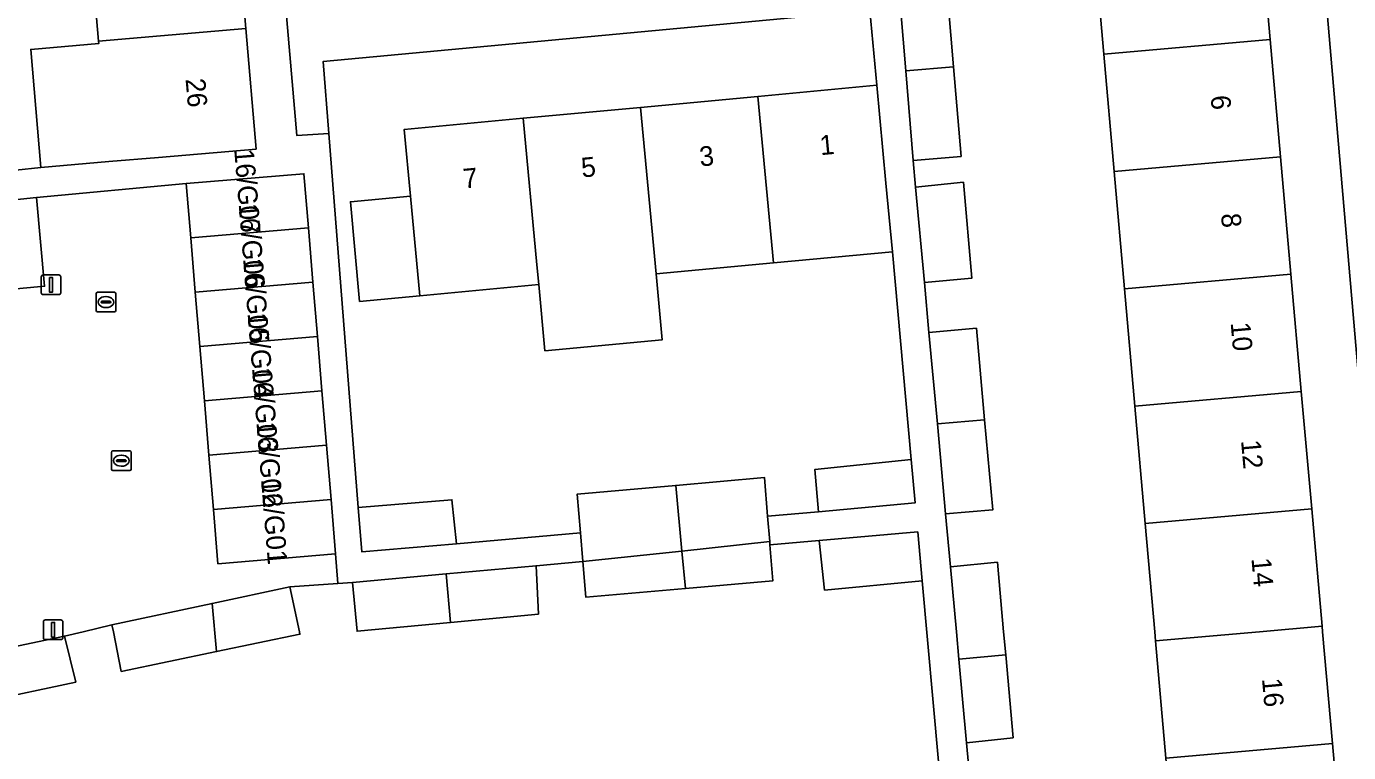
# Model space of a CAD drawing. Extents: x 160554 to 161248, y 385329 to 386506.
# Drawn here: x 160851.7 to 160919, y 385493.8 to 385530.8 of the extents above; entities that cross this region are included whole.
import ezdxf

# ---------------------------------------------------------------- set-up
doc = ezdxf.new("R2010")
doc.units = 0
for name, color, linetype in [('IMGEO_Erf', 7, 'Continuous'), ('IMGEO_Kolk', 7, 'Continuous'), ('IMGEO_Lichtmast', 7, 'Continuous'), ('IMGEO_Pand', 7, 'Continuous'), ('IMGEO_Pand_nummerreeks', 7, 'Continuous'), ('IMGEO_Rijbaan_lokaal_open', 7, 'Continuous'), ('IMGEO_Voetpad_open', 7, 'Continuous')]:
    doc.layers.add(name, color=color, linetype=linetype)

msp = doc.modelspace()

# ---------------------------------------------------------------- linework, layer by layer
at = {"layer": 'IMGEO_Erf'}
for points in [[(160847.33, 385523.103), (160852.438, 385523.647), (160851.923, 385529.66), (160855.383, 385529.957), (160855.372, 385530.081), (160854.859, 385536.059), (160854.347, 385542.038), (160853.835, 385548.016), (160853.735, 385549.177), (160853.308, 385554.158), (160850.795, 385554.015)], [(160922.169, 385482.49), (160920.66, 385500), (160917.04, 385541.995)], [(160898.533, 385533.424), (160898.921, 385528.774), (160899.302, 385524.209), (160896.864, 385524.005), (160896.988, 385522.65), (160899.419, 385522.893), (160899.857, 385518.014), (160897.434, 385517.787), (160897.668, 385515.238), (160900.086, 385515.454), (160900.503, 385510.798), (160900.915, 385506.204), (160898.514, 385506.003), (160898.761, 385503.314), (160901.154, 385503.536), (160901.471, 385500), (160901.577, 385498.816), (160901.955, 385494.597), (160899.584, 385494.338), (160899.871, 385491.211)], [(160898.156, 385493.385), (160897.322, 385502.59), (160892.348, 385502.123), (160892.083, 385504.64), (160889.57, 385504.418), (160889.721, 385502.597), (160885.262, 385502.205), (160880.193, 385501.759), (160880.036, 385503.585), (160877.659, 385503.363), (160877.777, 385500.899), (160873.294, 385500.473), (160868.541, 385500.022), (160868.309, 385502.512), (160867.569, 385502.46), (160865.12, 385502.288), (160865.605, 385500), (160865.632, 385499.874), (160861.382, 385498.99), (160856.532, 385497.982), (160856.127, 385500), (160856.058, 385500.345), (160854.586, 385500), (160853.634, 385499.777), (160854.211, 385497.44), (160849.566, 385496.443)]]:
    msp.add_lwpolyline(points, dxfattribs=at)
for points in [[(160907.099, 385523.44), (160906.571, 385529.417), (160906.043, 385535.394), (160905.5, 385541.541), (160913.975, 385542.309), (160914.52, 385536.143), (160915.048, 385530.166), (160915.575, 385524.189), (160916.103, 385518.213), (160916.631, 385512.236), (160917.159, 385506.259), (160917.687, 385500.282), (160917.712, 385500), (160918.215, 385494.306), (160918.76, 385488.141), (160910.284, 385487.387), (160909.739, 385493.557), (160909.211, 385499.533), (160909.17, 385500), (160908.683, 385505.51), (160908.155, 385511.487), (160907.627, 385517.464)], [(160895.804, 385519.357), (160889.741, 385518.792), (160883.767, 385518.234), (160884.08, 385514.87), (160878.105, 385514.314), (160877.792, 385517.677), (160871.731, 385517.112), (160868.671, 385516.827), (160868.198, 385521.898), (160871.258, 385522.184), (160870.94, 385525.585), (160877.003, 385526.15), (160882.978, 385526.708), (160888.952, 385527.265), (160895.014, 385527.83), (160894.659, 385531.64), (160866.822, 385529.049), (160867.099, 385525.38), (160868.589, 385506.326), (160873.368, 385506.726), (160873.599, 385504.474), (160879.912, 385505.035), (160879.743, 385507.006), (160884.773, 385507.454), (160889.284, 385507.856), (160889.448, 385505.888), (160892.046, 385506.113), (160891.849, 385508.261), (160896.763, 385508.775)]]:
    msp.add_lwpolyline(points, close=True, dxfattribs=at)
at = {"layer": 'IMGEO_Kolk'}
for p, q in [((160855.252, 385516.364), (160855.252, 385517.216)), ((160855.327, 385517.29), (160856.179, 385517.29)), ((160856.253, 385517.216), (160856.253, 385516.364)), ((160855.511, 385516.784), (160855.511, 385516.796)), ((160855.949, 385516.747), (160855.551, 385516.747)), ((160855.554, 385516.833), (160855.952, 385516.833)), ((160855.763, 385516.51), (160855.738, 385516.51)), ((160855.74, 385517.07), (160855.765, 385517.07)), ((160855.995, 385516.796), (160855.995, 385516.784)), ((160856.179, 385516.29), (160855.327, 385516.29)), ((160856.033, 385508.285), (160856.033, 385509.137)), ((160856.108, 385509.211), (160856.96, 385509.211)), ((160857.034, 385509.137), (160857.034, 385508.285)), ((160856.292, 385508.705), (160856.292, 385508.717)), ((160856.73, 385508.668), (160856.332, 385508.668)), ((160856.335, 385508.754), (160856.733, 385508.754)), ((160856.544, 385508.431), (160856.519, 385508.431)), ((160856.521, 385508.991), (160856.546, 385508.991)), ((160856.776, 385508.717), (160856.776, 385508.705)), ((160856.96, 385508.211), (160856.108, 385508.211))]:
    msp.add_line(p, q, dxfattribs=at)
for points in [[(160855.252, 385516.364), (160855.252, 385517.216)], [(160855.327, 385517.29), (160856.179, 385517.29)], [(160856.253, 385517.216), (160856.253, 385516.364)], [(160856.179, 385516.29), (160855.327, 385516.29)], [(160856.033, 385508.285), (160856.033, 385509.137)], [(160856.108, 385509.211), (160856.96, 385509.211)], [(160857.034, 385509.137), (160857.034, 385508.285)], [(160856.96, 385508.211), (160856.108, 385508.211)]]:
    msp.add_lwpolyline(points, dxfattribs=at)
for centre, radius, start, end in [((160855.329, 385517.214), 0.0765, 91.55205, 178.44795), ((160855.329, 385517.214), 0.0765, 91.55205, 178.44795), ((160856.177, 385517.214), 0.0765, 1.55205, 88.44795), ((160856.177, 385517.214), 0.0765, 1.55205, 88.44795), ((160855.551, 385516.793), 0.0403, 85.87752, 175.75265), ((160855.548, 385516.783), 0.0366, 178.93798, 274.71019), ((160855.952, 385516.79), 0.043, 264.86636, 352.45326), ((160855.956, 385516.795), 0.0386, 1.73085, 96.63898), ((160855.329, 385516.366), 0.0765, 181.55205, 268.44795), ((160855.329, 385516.366), 0.0765, 181.55205, 268.44795), ((160856.177, 385516.366), 0.0765, 271.55205, 358.44795), ((160856.177, 385516.366), 0.0765, 271.55205, 358.44795), ((160856.11, 385509.135), 0.0765, 91.55205, 178.44795), ((160856.11, 385509.135), 0.0765, 91.55205, 178.44795), ((160856.958, 385509.135), 0.0765, 1.55205, 88.44795), ((160856.958, 385509.135), 0.0765, 1.55205, 88.44795), ((160856.332, 385508.714), 0.0403, 85.87752, 175.75265), ((160856.329, 385508.704), 0.0366, 178.93798, 274.71019), ((160856.733, 385508.711), 0.043, 264.86636, 352.45326), ((160856.737, 385508.716), 0.0386, 1.73085, 96.63898), ((160856.11, 385508.287), 0.0765, 181.55205, 268.44795), ((160856.11, 385508.287), 0.0765, 181.55205, 268.44795), ((160856.958, 385508.287), 0.0765, 271.55205, 358.44795), ((160856.958, 385508.287), 0.0765, 271.55205, 358.44795)]:
    msp.add_arc(centre, radius, start, end, dxfattribs=at)
for centre, major_axis, ratio, start_param, end_param in [((160855.739, 385516.79), (-0.387, 0.002), 0.722429, 4.712389, 7.853982), ((160855.764, 385516.79), (-0.39, 0.002), 0.717154, 1.570796, 4.712389), ((160856.52, 385508.711), (-0.387, 0.002), 0.722429, 4.712389, 7.853982), ((160856.545, 385508.711), (-0.39, 0.002), 0.717154, 1.570796, 4.712389)]:
    msp.add_ellipse(centre, major_axis=major_axis, ratio=ratio, start_param=start_param, end_param=end_param, dxfattribs=at)
at = {"layer": 'IMGEO_Lichtmast'}
for p, q in [((160852.458, 385517.269), (160852.458, 385518.069)), ((160852.458, 385518.069), (160852.458, 385517.269)), ((160852.558, 385518.169), (160853.348, 385518.169)), ((160853.348, 385518.169), (160852.558, 385518.169)), ((160853.448, 385518.069), (160853.448, 385517.269)), ((160853.448, 385517.269), (160853.448, 385518.069)), ((160853.348, 385517.169), (160852.558, 385517.169)), ((160852.558, 385517.169), (160853.348, 385517.169)), ((160852.566, 385499.699), (160852.566, 385500.499)), ((160852.566, 385500.499), (160852.566, 385499.699)), ((160852.666, 385500.599), (160853.456, 385500.599)), ((160853.456, 385500.599), (160852.666, 385500.599)), ((160853.556, 385500.499), (160853.556, 385499.699)), ((160853.556, 385499.699), (160853.556, 385500.499)), ((160853.456, 385499.599), (160852.666, 385499.599)), ((160852.666, 385499.599), (160853.456, 385499.599))]:
    msp.add_line(p, q, dxfattribs=at)
for points in [[(160852.878, 385518.044), (160853.028, 385518.044), (160853.028, 385517.294), (160852.878, 385517.294), (160852.878, 385518.044)], [(160852.986, 385500.474), (160853.136, 385500.474), (160853.136, 385499.724), (160852.986, 385499.724), (160852.986, 385500.474)]]:
    msp.add_lwpolyline(points, dxfattribs=at)
for centre, start, end in [((160852.558, 385518.069), 90, 180), ((160852.558, 385518.069), 90, 180), ((160853.348, 385518.069), 0, 90), ((160853.348, 385518.069), 360, 90), ((160852.558, 385517.269), 180, 270), ((160852.558, 385517.269), 180, 270), ((160853.348, 385517.269), 270, 0), ((160853.348, 385517.269), 270, 0), ((160852.666, 385500.499), 90, 180), ((160852.666, 385500.499), 90, 180), ((160853.456, 385500.499), 0, 90), ((160853.456, 385500.499), 360, 90), ((160852.666, 385499.699), 180, 270), ((160852.666, 385499.699), 180, 270), ((160853.456, 385499.699), 270, 0), ((160853.456, 385499.699), 270, 0)]:
    msp.add_arc(centre, 0.1, start, end, dxfattribs=at)
at = {"layer": 'IMGEO_Pand'}
for points in [[(160862.874, 385530.724), (160862.361, 385536.702), (160854.859, 385536.059), (160855.372, 385530.081)], [(160906.043, 385535.394), (160906.571, 385529.417), (160915.048, 385530.166), (160914.52, 385536.143)], [(160896.215, 385531.785), (160896.484, 385528.559), (160898.921, 385528.774), (160898.533, 385533.424), (160896.095, 385533.221)], [(160862.874, 385530.724), (160855.372, 385530.081), (160855.383, 385529.957), (160851.923, 385529.66), (160852.438, 385523.647), (160855.898, 385523.943), (160858.419, 385524.159), (160863.4, 385524.586)], [(160915.575, 385524.189), (160915.048, 385530.166), (160906.571, 385529.417), (160907.099, 385523.44)], [(160896.484, 385528.559), (160896.864, 385524.005), (160899.302, 385524.209), (160898.921, 385528.774)], [(160888.952, 385527.265), (160882.978, 385526.708), (160883.767, 385518.234), (160889.741, 385518.792)], [(160889.741, 385518.792), (160895.804, 385519.357), (160895.478, 385522.852), (160895.014, 385527.83), (160888.952, 385527.265)], [(160882.978, 385526.708), (160877.003, 385526.15), (160877.699, 385518.679), (160877.792, 385517.677), (160878.105, 385514.314), (160884.08, 385514.87), (160883.767, 385518.234)], [(160877.003, 385526.15), (160870.94, 385525.585), (160871.258, 385522.184), (160871.731, 385517.112), (160877.792, 385517.677), (160877.699, 385518.679)], [(160907.099, 385523.44), (160907.627, 385517.464), (160916.103, 385518.213), (160915.575, 385524.189)], [(160865.831, 385523.329), (160859.84, 385522.83), (160860.07, 385520.064), (160866.061, 385520.563)], [(160899.857, 385518.014), (160899.419, 385522.893), (160896.988, 385522.65), (160897.434, 385517.787)], [(160848.46, 385517.218), (160852.623, 385517.592), (160852.215, 385522.108), (160848.142, 385521.699)], [(160871.258, 385522.184), (160868.198, 385521.898), (160868.671, 385516.827), (160871.731, 385517.112)], [(160860.07, 385520.064), (160860.301, 385517.297), (160866.292, 385517.796), (160866.061, 385520.563)], [(160866.522, 385515.03), (160866.292, 385517.796), (160860.301, 385517.297), (160860.531, 385514.531)], [(160916.631, 385512.236), (160916.103, 385518.213), (160907.627, 385517.464), (160908.155, 385511.487)], [(160900.503, 385510.798), (160900.086, 385515.454), (160897.668, 385515.238), (160898.094, 385510.585)], [(160866.753, 385512.263), (160866.522, 385515.03), (160860.531, 385514.531), (160860.762, 385511.764)], [(160866.983, 385509.497), (160866.753, 385512.263), (160860.762, 385511.764), (160860.992, 385508.998)], [(160917.159, 385506.259), (160916.631, 385512.236), (160908.155, 385511.487), (160908.683, 385505.51)], [(160898.094, 385510.585), (160898.514, 385506.003), (160900.915, 385506.204), (160900.503, 385510.798)], [(160860.992, 385508.998), (160861.223, 385506.231), (160867.214, 385506.73), (160866.983, 385509.497)], [(160896.763, 385508.775), (160891.849, 385508.261), (160892.046, 385506.113), (160896.963, 385506.564)], [(160889.555, 385504.595), (160889.448, 385505.888), (160889.284, 385507.856), (160884.773, 385507.454), (160885.085, 385504.103)], [(160885.085, 385504.103), (160884.773, 385507.454), (160879.743, 385507.006), (160879.912, 385505.035), (160880.036, 385503.585)], [(160861.223, 385506.231), (160861.453, 385503.465), (160867.444, 385503.964), (160867.214, 385506.73)], [(160868.589, 385506.326), (160868.778, 385504.072), (160873.599, 385504.474), (160873.368, 385506.726)], [(160908.683, 385505.51), (160909.17, 385500), (160909.211, 385499.533), (160914.495, 385500), (160917.687, 385500.282), (160917.159, 385506.259)], [(160892.083, 385504.64), (160892.348, 385502.123), (160897.322, 385502.59), (160897.097, 385505.081)], [(160889.57, 385504.418), (160889.56, 385504.54), (160889.555, 385504.595), (160885.085, 385504.103), (160885.262, 385502.205), (160889.721, 385502.597)], [(160880.036, 385503.585), (160880.193, 385501.759), (160885.262, 385502.205), (160885.085, 385504.103)], [(160873.294, 385500.473), (160877.777, 385500.899), (160877.659, 385503.363), (160873.07, 385502.945)], [(160899.065, 385500), (160899.193, 385498.606), (160901.577, 385498.816), (160901.471, 385500), (160901.154, 385503.536), (160898.761, 385503.314)], [(160873.07, 385502.945), (160868.309, 385502.512), (160868.541, 385500.022), (160873.294, 385500.473)], [(160861.382, 385498.99), (160865.632, 385499.874), (160865.605, 385500), (160865.12, 385502.288), (160861.16, 385501.439)], [(160861.16, 385501.439), (160856.058, 385500.345), (160856.127, 385500), (160856.532, 385497.982), (160861.382, 385498.99)], [(160918.215, 385494.306), (160917.712, 385500), (160917.687, 385500.282), (160914.495, 385500), (160909.211, 385499.533), (160909.739, 385493.557)], [(160849.566, 385496.443), (160854.211, 385497.44), (160853.634, 385499.777), (160849.345, 385498.873)], [(160899.584, 385494.338), (160901.955, 385494.597), (160901.577, 385498.816), (160899.193, 385498.606)], [(160909.739, 385493.557), (160910.284, 385487.387), (160918.76, 385488.141), (160918.215, 385494.306)]]:
    msp.add_lwpolyline(points, close=True, dxfattribs=at)
at = {"layer": 'IMGEO_Rijbaan_lokaal_open'}
msp.add_lwpolyline([(160849.345, 385498.873), (160853.634, 385499.777), (160854.586, 385500), (160856.058, 385500.345), (160861.16, 385501.439), (160865.12, 385502.288), (160867.569, 385502.46), (160867.444, 385503.964), (160861.453, 385503.465), (160861.223, 385506.231), (160860.992, 385508.998), (160860.762, 385511.764), (160860.531, 385514.531), (160860.301, 385517.297), (160860.07, 385520.064), (160859.84, 385522.83), (160852.215, 385522.108), (160852.623, 385517.592), (160848.46, 385517.218)], dxfattribs=at)
at = {"layer": 'IMGEO_Voetpad_open'}
for points in [[(160912.922, 385553.512), (160864.993, 385549.134), (160863.436, 385548.992), (160864.998, 385530.768), (160865.469, 385525.276), (160867.099, 385525.38), (160866.822, 385529.049), (160894.659, 385531.64), (160896.215, 385531.785), (160896.095, 385533.221), (160895.88, 385535.788), (160895.471, 385540.695)], [(160848.142, 385521.699), (160852.215, 385522.108), (160859.84, 385522.83), (160865.831, 385523.329), (160866.061, 385520.563), (160866.292, 385517.796), (160866.522, 385515.03), (160866.753, 385512.263), (160866.983, 385509.497), (160867.214, 385506.73), (160867.444, 385503.964), (160867.569, 385502.46), (160868.309, 385502.512), (160873.07, 385502.945), (160877.659, 385503.363), (160880.036, 385503.585), (160879.912, 385505.035), (160873.599, 385504.474), (160868.778, 385504.072), (160868.589, 385506.326), (160867.099, 385525.38), (160865.469, 385525.276), (160864.998, 385530.768), (160863.436, 385548.992)], [(160917.951, 385544.1), (160917.04, 385541.995), (160920.66, 385500), (160922.169, 385482.49), (160925.231, 385482.784), (160923.776, 385500), (160923.539, 385502.802), (160922.751, 385512.494)], [(160862.361, 385536.702), (160862.874, 385530.724), (160863.4, 385524.586), (160858.419, 385524.159), (160855.898, 385523.943), (160852.438, 385523.647), (160847.33, 385523.103)], [(160894.659, 385531.64), (160895.014, 385527.83), (160895.478, 385522.852), (160895.804, 385519.357), (160896.763, 385508.775), (160896.963, 385506.564), (160892.046, 385506.113), (160889.448, 385505.888), (160889.555, 385504.595), (160889.56, 385504.54), (160889.57, 385504.418), (160892.083, 385504.64), (160897.097, 385505.081), (160897.322, 385502.59), (160898.156, 385493.385)], [(160899.871, 385491.211), (160899.584, 385494.338), (160899.193, 385498.606), (160899.065, 385500), (160898.761, 385503.314), (160898.514, 385506.003), (160898.094, 385510.585), (160897.668, 385515.238), (160897.434, 385517.787), (160896.988, 385522.65), (160896.864, 385524.005), (160896.484, 385528.559), (160896.215, 385531.785)]]:
    msp.add_lwpolyline(points, dxfattribs=at)

# ---------------------------------------------------------------- texts
at = {"layer": 'IMGEO_Pand_nummerreeks'}
for s, rotation, p in [('26', 274.89858, (160859.804, 385528.151)), ('6', 275.0475, (160912.009, 385527.285)), ('1', 5.32766, (160892.149, 385524.269)), ('3', 5.32766, (160886.017, 385523.697)), ('16/G07', 274.65635, (160862.282, 385524.558)), ('5', 5.32851, (160879.999, 385523.135)), ('7', 5.32851, (160873.981, 385522.574)), ('16/G06', 274.65635, (160862.509, 385521.777)), ('8', 275.0475, (160912.539, 385521.277)), ('16/G05', 274.65635, (160862.735, 385518.995)), ('16/G04', 274.65635, (160862.962, 385516.213)), ('10', 275.0475, (160913.03, 385515.732)), ('16/G03', 274.65635, (160863.188, 385513.432)), ('16/G02', 274.65635, (160863.414, 385510.656)), ('12', 275.0475, (160913.559, 385509.735)), ('16/G01', 274.65635, (160863.65, 385507.758)), ('14', 275.0475, (160914.089, 385503.728)), ('16', 275.07845, (160914.626, 385497.605))]:
    msp.add_text(s, height=1, rotation=rotation, dxfattribs=at).set_placement(p)

doc.saveas('drawing.dxf')
